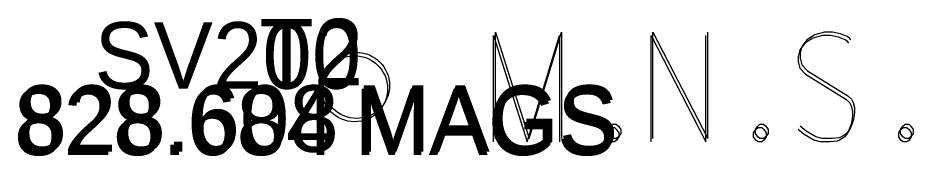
# Model space of a CAD drawing. Extents: x 1455931 to 1456172, y 560190 to 560355.
# Drawn here: x 1456023.99 to 1456037.46, y 560352.53 to 560354.61 of the extents above; entities that cross this region are included whole.
import ezdxf

# ---------------------------------------------------------------- set-up
doc = ezdxf.new("R2010")
doc.units = 0
for name, color, linetype in [('SV_P_Control_Cells_Set', 7, 'Continuous'), ('SV_X_Text_Comment', 7, 'Continuous'), ('SV_X_Text_Elevation', 7, 'Continuous'), ('SV_X_Text_Name', 7, 'Continuous')]:
    doc.layers.add(name, color=color, linetype=linetype)

msp = doc.modelspace()

# ---------------------------------------------------------------- linework, layer by layer
at = {"layer": 'SV_P_Control_Cells_Set'}
for points in [[(1456031.175, 560352.797), (1456031.175, 560354.397), (1456031.682, 560352.797), (1456032.167, 560354.397), (1456032.167, 560352.797)], [(1456033.545, 560352.797), (1456033.545, 560354.397), (1456034.372, 560352.797), (1456034.372, 560354.397)], [(1456036.522, 560354.284), (1456036.5, 560354.309), (1456036.466, 560354.334), (1456036.367, 560354.372), (1456036.246, 560354.397), (1456036.158, 560354.397), (1456036.125, 560354.397), (1456035.981, 560354.36), (1456035.86, 560354.284), (1456035.783, 560354.183), (1456035.761, 560354.082), (1456035.761, 560354.007), (1456035.783, 560353.906), (1456035.871, 560353.818), (1456036.478, 560353.44), (1456036.533, 560353.39), (1456036.555, 560353.339), (1456036.577, 560353.264), (1456036.577, 560353.188), (1456036.566, 560353.112), (1456036.555, 560353.062), (1456036.533, 560352.999), (1456036.511, 560352.949), (1456036.488, 560352.911), (1456036.455, 560352.873), (1456036.422, 560352.848), (1456036.378, 560352.823), (1456036.345, 560352.81), (1456036.246, 560352.797), (1456036.092, 560352.797), (1456035.993, 560352.823), (1456035.849, 560352.911), (1456035.761, 560352.986)], [(1456031.146, 560352.747), (1456031.146, 560354.347), (1456031.653, 560352.747), (1456032.138, 560354.347), (1456032.138, 560352.747)], [(1456033.516, 560352.747), (1456033.516, 560354.347), (1456034.343, 560352.747), (1456034.343, 560354.347)], [(1456036.493, 560354.234), (1456036.471, 560354.259), (1456036.437, 560354.284), (1456036.338, 560354.322), (1456036.217, 560354.347), (1456036.129, 560354.347), (1456036.096, 560354.347), (1456035.952, 560354.31), (1456035.831, 560354.234), (1456035.754, 560354.133), (1456035.732, 560354.032), (1456035.732, 560353.957), (1456035.754, 560353.856), (1456035.842, 560353.768), (1456036.449, 560353.39), (1456036.504, 560353.34), (1456036.526, 560353.289), (1456036.548, 560353.214), (1456036.548, 560353.138), (1456036.537, 560353.062), (1456036.526, 560353.012), (1456036.504, 560352.949), (1456036.482, 560352.899), (1456036.459, 560352.861), (1456036.426, 560352.823), (1456036.393, 560352.798), (1456036.349, 560352.773), (1456036.316, 560352.76), (1456036.217, 560352.747), (1456036.063, 560352.747), (1456035.964, 560352.773), (1456035.82, 560352.861), (1456035.732, 560352.936)], [(1456032.91, 560352.962), (1456032.965, 560352.962), (1456032.998, 560352.936), (1456033.031, 560352.886), (1456033.031, 560352.823), (1456032.998, 560352.773), (1456032.965, 560352.747), (1456032.91, 560352.747), (1456032.877, 560352.773), (1456032.844, 560352.823), (1456032.844, 560352.886), (1456032.877, 560352.936), (1456032.91, 560352.962)], [(1456032.939, 560353.012), (1456032.994, 560353.012), (1456033.027, 560352.986), (1456033.06, 560352.936), (1456033.06, 560352.873), (1456033.027, 560352.823), (1456032.994, 560352.797), (1456032.939, 560352.797), (1456032.906, 560352.823), (1456032.873, 560352.873), (1456032.873, 560352.936), (1456032.906, 560352.986), (1456032.939, 560353.012)], [(1456035.126, 560352.962), (1456035.181, 560352.962), (1456035.214, 560352.936), (1456035.247, 560352.886), (1456035.247, 560352.823), (1456035.214, 560352.773), (1456035.181, 560352.747), (1456035.126, 560352.747), (1456035.093, 560352.773), (1456035.06, 560352.823), (1456035.06, 560352.886), (1456035.093, 560352.936), (1456035.126, 560352.962)], [(1456035.155, 560353.012), (1456035.21, 560353.012), (1456035.243, 560352.986), (1456035.276, 560352.936), (1456035.276, 560352.873), (1456035.243, 560352.823), (1456035.21, 560352.797), (1456035.155, 560352.797), (1456035.122, 560352.823), (1456035.089, 560352.873), (1456035.089, 560352.936), (1456035.122, 560352.986), (1456035.155, 560353.012)], [(1456037.308, 560352.962), (1456037.363, 560352.962), (1456037.397, 560352.936), (1456037.429, 560352.886), (1456037.429, 560352.823), (1456037.397, 560352.773), (1456037.363, 560352.747), (1456037.308, 560352.747), (1456037.275, 560352.773), (1456037.242, 560352.823), (1456037.242, 560352.886), (1456037.275, 560352.936), (1456037.308, 560352.962)], [(1456037.337, 560353.012), (1456037.392, 560353.012), (1456037.426, 560352.986), (1456037.458, 560352.936), (1456037.458, 560352.873), (1456037.426, 560352.823), (1456037.392, 560352.797), (1456037.337, 560352.797), (1456037.304, 560352.823), (1456037.271, 560352.873), (1456037.271, 560352.936), (1456037.304, 560352.986), (1456037.337, 560353.012)]]:
    msp.add_lwpolyline(points, dxfattribs=at)
for centre in [(1456029.057, 560353.547), (1456029.086, 560353.597)]:
    msp.add_circle(centre, 0.497, dxfattribs=at)

# ---------------------------------------------------------------- texts
at = {"layer": 'SV_X_Text_Comment'}
for p in [(1456029.085, 560352.598), (1456029.056, 560352.548)]:
    msp.add_text('MAGS', height=1, dxfattribs=at).set_placement(p)
at = {"layer": 'SV_X_Text_Elevation'}
for s, p in [('828.608', (1456023.985, 560352.598)), ('828.684', (1456023.934, 560352.548))]:
    msp.add_text(s, height=1, dxfattribs=at).set_placement(p)
at = {"layer": 'SV_X_Text_Name'}
for s, p in [('SV200', (1456025.142, 560353.548)), ('T2', (1456027.626, 560353.598))]:
    msp.add_text(s, height=1, dxfattribs=at).set_placement(p)

doc.saveas('drawing.dxf')
